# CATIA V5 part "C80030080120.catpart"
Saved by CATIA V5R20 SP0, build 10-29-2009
Part number: C80030080120
Source: Unknown
Property "A": "90"
Property "ARTICLENO": "C80030080120"
Property "B": "45"
Property "BOMINFO": "C80030080120"
Property "C": "130"
Property "CA": "C80030080120"
Property "D1": "170"
Property "DES": "ROTATING EYEBOLT WITH RING Ton 30 M80x120"
Property "E": "165"
Property "H": "338"
Property "L": "120"
Property "LINA": "C80030080120"
Property "NB": "C80030080120"
Property "NBSYN": "$CODE."
Property "NN": "C800"
Property "NT": "Rotating eyebolt with ring"
Property "SIZE": "M80"
Property "SUPPLIER": "CF"
Property "SW": "134"
Property "WEIGHT": "29000"
Property "WLL": "30.00"
Bounding box of the stored display mesh (mm): x -90 to 90, y -120 to 383, z -85 to 85
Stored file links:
  C:\Users\Utente\Desktop\3D files 800\C80030080120.catpart
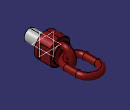
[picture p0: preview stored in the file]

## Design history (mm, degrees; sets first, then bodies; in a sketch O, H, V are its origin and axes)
Body1 "Geometry.1" (main body)
  Solid1 "C80030080120.catpart": solid without history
